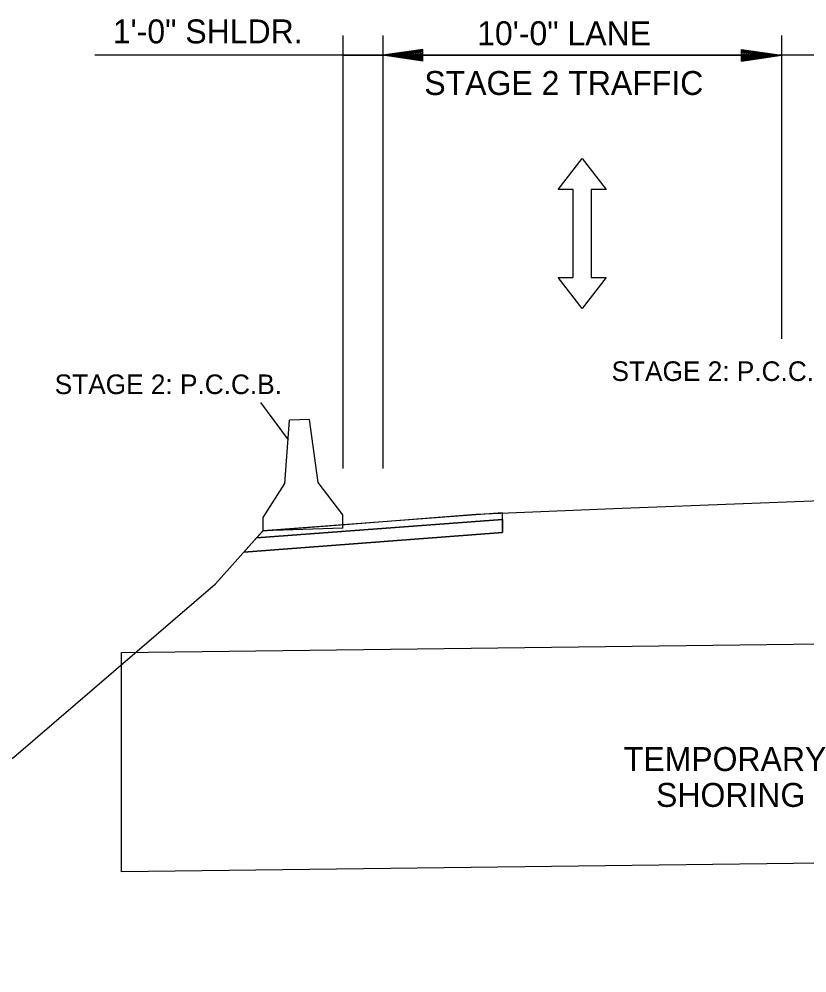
# Model space of a CAD drawing. Extents: x 1398460 to 1408037, y 380768 to 383968.
# Drawn here: x 1399645.4 to 1399843.1, y 383119.2 to 383358.4 of the extents above; entities that cross this region are included whole.
import ezdxf

# ---------------------------------------------------------------- set-up
doc = ezdxf.new("R2010")
doc.units = 0
for name, color, linetype in [('Default', 7, 'Continuous'), ('R_Dimension', 7, 'Continuous'), ('R_Draft', 7, 'Continuous'), ('R_Exist Surface', 7, 'Continuous'), ('R_Striping', 7, 'Continuous'), ('R_Water', 7, 'Continuous')]:
    doc.layers.add(name, color=color, linetype=linetype)

msp = doc.modelspace()

# ---------------------------------------------------------------- linework, layer by layer
at = {"layer": 'Default'}
for p, q in [((1399712.11, 383241.97), (1399713.26, 383257.85)), ((1399715.76, 383257.93), (1399713.26, 383257.85)), ((1399718.26, 383258.01), (1399715.76, 383257.93)), ((1399720.44, 383242.24), (1399718.26, 383258.01)), ((1399706.62, 383233.45), (1399712.11, 383241.97)), ((1399726.62, 383234.1), (1399720.44, 383242.24)), ((1399706.66, 383230.12), (1399706.62, 383233.45)), ((1399726.66, 383230.77), (1399726.62, 383234.1)), ((1399726.66, 383230.77), (1399706.66, 383230.12))]:
    msp.add_line(p, q, dxfattribs=at)
at = {"layer": 'R_Dimension'}
for p, q in [((1399726.67, 383354.35), (1399726.67, 383245.72)), ((1399736.67, 383354.35), (1399736.67, 383245.72)), ((1399836.67, 383354.35), (1399836.67, 383278.26)), ((1399746.67, 383350.85), (1399736.67, 383349.35)), ((1399746.67, 383350.6), (1399738.34, 383349.35)), ((1399746.67, 383350.35), (1399740.06, 383349.35)), ((1399746.67, 383350.1), (1399741.72, 383349.35)), ((1399746.67, 383349.84), (1399743.42, 383349.35)), ((1399746.67, 383349.59), (1399745.09, 383349.35)), ((1399746.67, 383347.85), (1399746.67, 383350.85)), ((1399826.67, 383350.85), (1399836.67, 383349.35)), ((1399826.67, 383347.85), (1399826.67, 383350.85)), ((1399826.67, 383350.6), (1399835, 383349.35)), ((1399826.67, 383350.35), (1399833.28, 383349.35)), ((1399826.67, 383350.1), (1399831.61, 383349.35)), ((1399826.67, 383349.84), (1399829.92, 383349.35)), ((1399826.67, 383349.59), (1399828.25, 383349.35)), ((1399921.97, 383349.35), (1399664.43, 383349.35)), ((1399746.67, 383347.85), (1399736.67, 383349.35)), ((1399746.67, 383348.1), (1399738.34, 383349.35)), ((1399746.67, 383348.36), (1399740.06, 383349.35)), ((1399746.67, 383348.61), (1399741.72, 383349.35)), ((1399746.67, 383348.87), (1399743.42, 383349.35)), ((1399746.67, 383349.12), (1399745.09, 383349.35)), ((1399826.67, 383347.85), (1399836.67, 383349.35)), ((1399826.67, 383348.87), (1399829.92, 383349.35)), ((1399826.67, 383348.36), (1399833.28, 383349.35)), ((1399826.67, 383348.1), (1399835, 383349.35)), ((1399826.67, 383348.61), (1399831.61, 383349.35)), ((1399826.67, 383349.12), (1399828.25, 383349.35)), ((1399706.02, 383262.27), (1399712.9, 383252.92)), ((1399766.67, 383232.92), (1399705.01, 383228.3)), ((1399766.67, 383229.62), (1399701.84, 383224.76))]:
    msp.add_line(p, q, dxfattribs=at)
for points in [[(1399766.67, 383234.62), (1399706.64, 383230.12), (1399705.01, 383228.3), (1399766.67, 383232.92)], [(1399766.67, 383232.92), (1399766.67, 383229.62), (1399701.84, 383224.76), (1399705.01, 383228.3)]]:
    msp.add_lwpolyline(points, close=True, dxfattribs=at)
for points in [[(1399766.67, 383234.62), (1399706.64, 383230.12), (1399705.01, 383228.3), (1399766.67, 383232.92), (1399766.67, 383234.62)], [(1399705.01, 383228.3), (1399701.84, 383224.76), (1399766.67, 383229.62), (1399766.67, 383232.92), (1399705.01, 383228.3)]]:
    msp.add_lwpolyline(points, dxfattribs=at)
at = {"layer": 'R_Draft'}
msp.add_line((1399726.67, 383349.35), (1399826.67, 383349.35), dxfattribs=at)
at = {"layer": 'R_Exist Surface'}
msp.add_lwpolyline([(1399228.4, 383169.53), (1399274.79, 383147.11), (1399308.64, 383124.96), (1399413.54, 383125.95), (1399518.92, 383119.19), (1399564.54, 383123.9), (1399570.04, 383124.42), (1399644.13, 383173.31), (1399694.66, 383216.79), (1399706.58, 383230.11), (1399724, 383231.42), (1399760.08, 383234.25), (1399794.58, 383235.67), (1399863.93, 383238.34), (1399899.16, 383238.15), (1399963.63, 383237.42), (1399999.02, 383235.82), (1400017.72, 383234.96), (1400035.29, 383232.19), (1400037.12, 383231.82), (1400040.35, 383227.25), (1400054.83, 383215.12), (1400141.21, 383139.52)], dxfattribs=at)
at = {"layer": 'R_Striping'}
msp.add_lwpolyline([(1399780.67, 383315.7), (1399786.67, 383323.49), (1399792.67, 383315.7), (1399788.92, 383315.7), (1399788.92, 383293.64), (1399792.67, 383293.64), (1399786.67, 383285.85), (1399780.67, 383293.64), (1399784.42, 383293.64), (1399784.42, 383315.7)], close=True, dxfattribs=at)
at = {"layer": 'R_Water'}
msp.add_lwpolyline([(1399866.67, 383146.99), (1399671.14, 383144.55), (1399671.14, 383199.56), (1399866.67, 383202)], dxfattribs=at)

# ---------------------------------------------------------------- texts
at = {"layer": 'R_Dimension'}
for s, p in [('1\'-0" SHLDR.', (1399668.92, 383352.35)), ('10\'-0" LANE', (1399760.33, 383351.89)), ('STAGE 2 TRAFFIC', (1399747.08, 383339.41)), ('TEMPORARY', (1399797.11, 383169.84)), ('SHORING', (1399805.21, 383160.84))]:
    msp.add_text(s, height=6, dxfattribs=at).set_placement(p)
at = {"layer": 'R_Draft'}
for p in [(1399794.05, 383267.67), (1399654.35, 383264.38)]:
    msp.add_text('STAGE 2: P.C.C.B.', height=4.9184, dxfattribs=at).set_placement(p)

doc.saveas('drawing.dxf')
